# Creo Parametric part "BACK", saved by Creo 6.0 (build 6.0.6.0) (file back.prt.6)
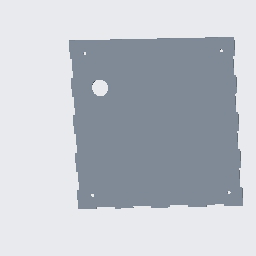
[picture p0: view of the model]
Units: Inch lbm Second (Pro/E Default); INCH, POUND, SECS

Created from: INLBS_PART_SOLID.PRT

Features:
  1. datum plane "RIGHT"
  2. datum plane "TOP"
  3. datum plane "FRONT"
  4. coordinate system
  5. sketch "Sketch 1"
  6. extrusion "Extrude 1"
  7. sketch "Sketch 3"
  8. sketch "Sketch 4"
  9. extruded cut "Extrude 3"
  10. sketch "Sketch 5"
  11. extruded cut "Extrude 4"

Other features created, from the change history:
  extruded cut "Extrude 2"
  sketch "Sketch 4"
  extruded cut "Extrude 3"

Surfaces: 54 plane, 5 cylinder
